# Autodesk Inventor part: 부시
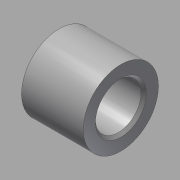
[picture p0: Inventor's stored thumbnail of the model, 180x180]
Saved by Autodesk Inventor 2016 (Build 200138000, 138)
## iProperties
Created: 2016-10
Part Number: 부시
Material: 강철, 연강
Document SubType Name: Modeling
Designer: mduedu
Density: 1 g/cm^3
Appearance: 강철
Author: mduedu
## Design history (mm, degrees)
sketch "스케치1"
  geometry: C1 r 14 at (0, 0); C2 r 8.5 at (0, 0); 1 further point
  constraints: 2 centre point, 2 coincident
  dimensions: "d0" = 28 diameter of C1; "d1" = 17 diameter of C2
extrude "돌출1" new body sketch "스케치1" distance "d2" = 23; taper "d3" = 0 deg
chamfer "모따기1" distance "d4" = 1; stored, may be unused: second distance "d5" = 2, angle "d6" = 45 deg
node "솔리드1"
